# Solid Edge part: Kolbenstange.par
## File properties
Username: ahadarics
Dokumentum tartalom típus: 0
Author: ahadarics
Last saved by: ahadarics
Revision: 81
Sűrűség: 0,000 kg/m^3
Pontosság: 0,990
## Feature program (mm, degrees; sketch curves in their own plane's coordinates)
base feature "unnamed BaseFeature 1"
thread "unnamed Thread 1"
sketch for "Kihúzás_1" plane through (59.75, 0, 0) normal (1, 0, 0) x-axis (0, -1, 0)
  circle centre (0, 0) radius 10
extrude "Kihúzás_1" add finite 32 along -normal
chamfer "Letörés_1" setback 0.4
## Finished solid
Body 1: solid body, 13 faces, 23 edges, 12 vertices.
  Faces by surface: plane 9, cylinder 3, cone 1
  Edges by curve: line 12, circle 11
Bounding box of the edges (mm): 218.500 x 20.000 x 20.000, from (-158.75, -10, -10) to (59.75, 10, 10).
Cylindrical faces by radius (mm): R4 x2, R10 x1
Conical faces (half-angle, radius in mm at the cone's reference point): 45 deg R3.6 x1
Planar faces by outward normal: +x 3, +z 1, -x 4, -z 1
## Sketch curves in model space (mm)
circle centre (59.75, 0, 0) radius 10
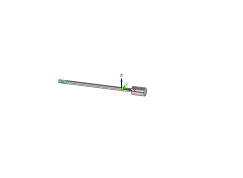
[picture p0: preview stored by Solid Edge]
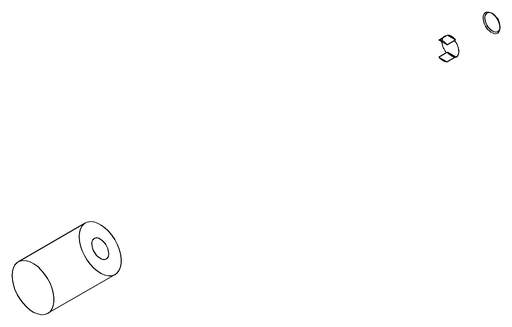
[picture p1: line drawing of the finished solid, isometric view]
